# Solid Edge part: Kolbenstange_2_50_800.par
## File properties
Username: ahadarics
Dokumentum tartalom típus: 0
Author: ahadarics
Last saved by: ahadarics
Revision: 91
Sűrűség: 0,000 kg/m^3
Pontosság: 0,990
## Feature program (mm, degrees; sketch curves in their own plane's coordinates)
base feature "unnamed BaseFeature 1"
thread "unnamed Thread 1"
chamfer "Letörés_1"  SetBackValue2 = 20 deg
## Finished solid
Body 1: solid body, 20 faces, 35 edges, 19 vertices.
  Faces by surface: plane 8, cylinder 5, torus 4, cone 3
  Edges by curve: circle 19, line 10, curve on surface 4, ellipse 2
Bounding box of the edges (mm; curved faces can reach further): 50.000 x 50.000 x 901.000, from (-25, -25, -63.5) to (25, 25, 837.5).
Cylindrical faces by radius (mm): R6.75 x1, R8 x1, R9.75 x1, R10 x1, R25 x1
Conical faces (half-angle, radius in mm at the cone's reference point): 20 deg R6.5004 x1, 30 deg R9.875 x1, 60 deg R7.375 x1
Toroidal faces (ring radius, tube radius in mm): R7.15 r0.4 x2, R8.55 r1.2 x2
Planar faces by outward normal: +x 1, +z 3, -x 1, -z 1, oblique 2
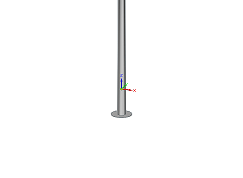
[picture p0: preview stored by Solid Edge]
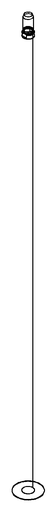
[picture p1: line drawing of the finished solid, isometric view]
